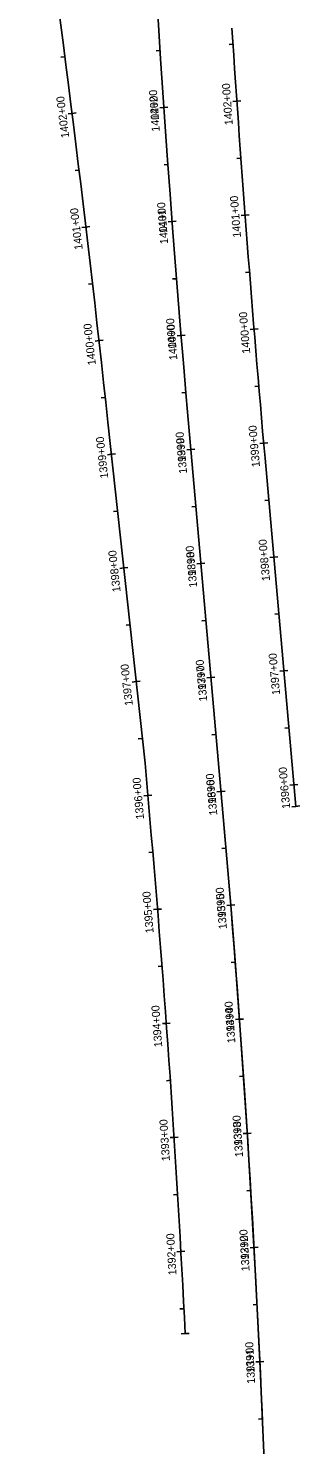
# Model space of a CAD drawing. Extents: x 596007 to 607538, y 326212 to 405053.
# Drawn here: x 602732 to 602976, y 363390 to 364628 of the extents above; entities that cross this region are included whole.
import ezdxf

# ---------------------------------------------------------------- set-up
doc = ezdxf.new("R2010")
doc.units = 0
doc.layers.add('P_ALI_200', color=7, linetype='Continuous')
doc.layers.add('P_ALI_200_Sta', color=7, linetype='Continuous')

msp = doc.modelspace()

# ---------------------------------------------------------------- linework, layer by layer
at = {"layer": 'P_ALI_200'}
for points in [[(602833.8, 363985.7), (602801.4, 364284)], [(602901.8, 363942.4), (602874.9, 364246.9)], [(602901.8, 363942.4), (602874.9, 364246.9)], [(602965.6, 363948), (602938.7, 364252.5)], [(602838.1, 363936.8), (602833.8, 363985.7)]]:
    msp.add_lwpolyline(points, dxfattribs=at)
for centre, radius, start, end in [((619326.8, 365700.7), 16516, 171.89148, 185.04999), ((619326.8, 365700.7), 16516, 171.89148, 185.04999), ((586893.5, 362570), 16000, 6.14964, 8.15156), ((619326.8, 365700.7), 16452, 183.73726, 185.04999), ((591430.5, 362928.7), 11452, 2.79426, 5.05), ((591430.5, 362928.7), 11516, 352.14213, 5.04999), ((591430.5, 362928.7), 11516, 2.35393, 5.04999)]:
    msp.add_arc(centre, radius, start, end, dxfattribs=at)
at = {"layer": 'P_ALI_200_Sta'}
for points in [[(602846.9, 364608.9), (602843.4, 364608.7)], [(602846.9, 364608.9), (602843.4, 364608.7)], [(602910.7, 364614.6), (602907.2, 364614.3)], [(602763.7, 364603.5), (602760.3, 364603.1)], [(602773.5, 364554.3), (602770, 364553.9)], [(602850.3, 364559), (602846.8, 364558.8)], [(602850.3, 364559), (602846.8, 364558.8)], [(602853.8, 364559.3), (602850.3, 364559)], [(602853.8, 364559.3), (602850.3, 364559)], [(602850.3, 364559), (602850.3, 364559)], [(602850.3, 364559), (602850.3, 364559)], [(602914.1, 364564.7), (602910.6, 364564.4)], [(602917.6, 364564.9), (602914.1, 364564.7)], [(602914.1, 364564.7), (602914.1, 364564.7)], [(602770, 364553.9), (602766.5, 364553.5)], [(602770, 364553.9), (602770, 364553.9)], [(602853.9, 364509.2), (602850.4, 364508.9)], [(602853.9, 364509.2), (602850.4, 364508.9)], [(602917.6, 364514.8), (602914.1, 364514.6)], [(602776.1, 364504.3), (602772.7, 364503.9)], [(602857.5, 364459.3), (602854, 364459)], [(602857.5, 364459.3), (602854, 364459)], [(602861, 364459.6), (602857.5, 364459.3)], [(602861, 364459.6), (602857.5, 364459.3)], [(602857.5, 364459.3), (602857.5, 364459.3)], [(602857.5, 364459.3), (602857.5, 364459.3)], [(602921.3, 364464.9), (602917.8, 364464.7)], [(602924.8, 364465.2), (602921.3, 364464.9)], [(602921.3, 364464.9), (602921.3, 364464.9)], [(602782.1, 364454.6), (602778.6, 364454.2)], [(602785.6, 364455.1), (602782.1, 364454.6)], [(602782.1, 364454.6), (602782.1, 364454.6)], [(602861.4, 364409.4), (602857.9, 364409.2)], [(602861.4, 364409.4), (602857.9, 364409.2)], [(602925.1, 364415.1), (602921.6, 364414.8)], [(602787.9, 364405), (602784.4, 364404.6)], [(602865.4, 364359.6), (602861.9, 364359.3)], [(602865.4, 364359.6), (602861.9, 364359.3)], [(602868.8, 364359.9), (602865.4, 364359.6)], [(602868.8, 364359.9), (602865.4, 364359.6)], [(602865.4, 364359.6), (602865.4, 364359.6)], [(602865.4, 364359.6), (602865.4, 364359.6)], [(602929.1, 364365.2), (602925.6, 364365)], [(602932.6, 364365.5), (602929.1, 364365.2)], [(602929.1, 364365.2), (602929.1, 364365.2)], [(602793.6, 364355.3), (602790.1, 364354.9)], [(602797.1, 364355.7), (602793.6, 364355.3)], [(602793.6, 364355.3), (602793.6, 364355.3)], [(602869.5, 364309.8), (602866, 364309.5)], [(602869.5, 364309.8), (602866, 364309.5)], [(602933.2, 364315.4), (602929.8, 364315.1)], [(602799.1, 364305.6), (602795.6, 364305.2)], [(602873.8, 364260), (602870.3, 364259.7)], [(602873.8, 364260), (602870.3, 364259.7)], [(602877.3, 364260.3), (602873.8, 364260)], [(602877.3, 364260.3), (602873.8, 364260)], [(602873.8, 364260), (602873.8, 364260)], [(602873.8, 364260), (602873.8, 364260)], [(602937.5, 364265.6), (602934, 364265.3)], [(602941, 364265.9), (602937.5, 364265.6)], [(602937.5, 364265.6), (602937.5, 364265.6)], [(602804.5, 364255.9), (602801, 364255.5)], [(602807.9, 364256.3), (602804.5, 364255.9)], [(602804.5, 364255.9), (602804.5, 364255.9)], [(602878.2, 364210.2), (602874.7, 364209.8)], [(602878.2, 364210.2), (602874.7, 364209.8)], [(602941.9, 364215.8), (602938.4, 364215.5)], [(602809.9, 364206.2), (602806.4, 364205.8)], [(602882.6, 364160.3), (602879.1, 364160)], [(602882.6, 364160.3), (602879.1, 364160)], [(602886.1, 364160.7), (602882.6, 364160.3)], [(602886.1, 364160.7), (602882.6, 364160.3)], [(602882.6, 364160.3), (602882.6, 364160.3)], [(602882.6, 364160.3), (602882.6, 364160.3)], [(602946.3, 364166), (602942.8, 364165.7)], [(602949.8, 364166.3), (602946.3, 364166)], [(602946.3, 364166), (602946.3, 364166)], [(602815.2, 364156.5), (602811.8, 364156.1)], [(602818.7, 364156.9), (602815.2, 364156.5)], [(602815.2, 364156.5), (602815.2, 364156.5)], [(602887, 364110.5), (602883.5, 364110.2)], [(602887, 364110.5), (602883.5, 364110.2)], [(602950.7, 364116.2), (602947.2, 364115.9)], [(602820.6, 364106.8), (602817.2, 364106.4)], [(602891.4, 364060.7), (602887.9, 364060.4)], [(602891.4, 364060.7), (602887.9, 364060.4)], [(602894.9, 364061), (602891.4, 364060.7)], [(602894.9, 364061), (602891.4, 364060.7)], [(602891.4, 364060.7), (602891.4, 364060.7)], [(602891.4, 364060.7), (602891.4, 364060.7)], [(602955.1, 364066.4), (602951.6, 364066.1)], [(602958.6, 364066.7), (602955.1, 364066.4)], [(602955.1, 364066.4), (602955.1, 364066.4)], [(602826, 364057.1), (602822.5, 364056.7)], [(602829.5, 364057.4), (602826, 364057.1)], [(602826, 364057.1), (602826, 364057.1)], [(602895.8, 364010.9), (602892.3, 364010.6)], [(602895.8, 364010.9), (602892.3, 364010.6)], [(602959.5, 364016.6), (602956, 364016.3)], [(602831.4, 364007.4), (602827.9, 364007)], [(602900.2, 363961.1), (602896.7, 363960.8)], [(602900.2, 363961.1), (602896.7, 363960.8)], [(602903.7, 363961.4), (602900.2, 363961.1)], [(602903.7, 363961.4), (602900.2, 363961.1)], [(602900.2, 363961.1), (602900.2, 363961.1)], [(602900.2, 363961.1), (602900.2, 363961.1)], [(602963.9, 363966.8), (602960.4, 363966.5)], [(602967.4, 363967.1), (602963.9, 363966.8)], [(602963.9, 363966.8), (602963.9, 363966.8)], [(602836.2, 363957.6), (602832.8, 363957.3)], [(602839.7, 363957.9), (602836.2, 363957.6)], [(602836.2, 363957.6), (602836.2, 363957.6)], [(602965.6, 363948), (602962.1, 363947.7)], [(602969.1, 363948.3), (602965.6, 363948)], [(602965.6, 363948), (602965.6, 363948)], [(602904.5, 363911.3), (602901, 363911)], [(602904.5, 363911.3), (602901, 363911)], [(602840.6, 363907.8), (602837.1, 363907.5)], [(602908.7, 363861.5), (602905.2, 363861.2)], [(602908.7, 363861.5), (602905.2, 363861.2)], [(602912.2, 363861.8), (602908.7, 363861.5)], [(602912.2, 363861.8), (602908.7, 363861.5)], [(602908.7, 363861.5), (602908.7, 363861.5)], [(602908.7, 363861.5), (602908.7, 363861.5)], [(602844.8, 363858), (602841.3, 363857.7)], [(602848.3, 363858.2), (602844.8, 363858)], [(602844.8, 363858), (602844.8, 363858)], [(602912.6, 363811.6), (602909.1, 363811.4)], [(602912.6, 363811.6), (602909.1, 363811.4)], [(602848.7, 363808.1), (602845.2, 363807.8)], [(602916.4, 363761.8), (602912.9, 363761.5)], [(602916.4, 363761.8), (602912.9, 363761.5)], [(602919.9, 363762), (602916.4, 363761.8)], [(602919.9, 363762), (602916.4, 363761.8)], [(602916.4, 363761.8), (602916.4, 363761.8)], [(602916.4, 363761.8), (602916.4, 363761.8)], [(602852.4, 363758.2), (602849, 363758)], [(602855.9, 363758.5), (602852.4, 363758.2)], [(602852.4, 363758.2), (602852.4, 363758.2)], [(602856, 363708.4), (602852.5, 363708.1)], [(602919.9, 363711.9), (602916.4, 363711.7)], [(602919.9, 363711.9), (602916.4, 363711.7)], [(602859.3, 363658.5), (602855.8, 363658.3)], [(602862.7, 363658.7), (602859.3, 363658.5)], [(602859.3, 363658.5), (602859.3, 363658.5)], [(602923.2, 363662), (602919.7, 363661.8)], [(602923.2, 363662), (602919.7, 363661.8)], [(602926.7, 363662.2), (602923.2, 363662)], [(602926.7, 363662.2), (602923.2, 363662)], [(602923.2, 363662), (602923.2, 363662)], [(602923.2, 363662), (602923.2, 363662)], [(602862.3, 363608.6), (602858.8, 363608.4)], [(602926.2, 363612.1), (602922.7, 363611.9)], [(602926.2, 363612.1), (602922.7, 363611.9)], [(602865.2, 363558.7), (602861.7, 363558.5)], [(602868.7, 363558.9), (602865.2, 363558.7)], [(602865.2, 363558.7), (602865.2, 363558.7)], [(602929.1, 363562.2), (602925.6, 363562)], [(602929.1, 363562.2), (602925.6, 363562)], [(602932.6, 363562.4), (602929.1, 363562.2)], [(602932.6, 363562.4), (602929.1, 363562.2)], [(602929.1, 363562.2), (602929.1, 363562.2)], [(602929.1, 363562.2), (602929.1, 363562.2)], [(602867.8, 363508.7), (602864.3, 363508.6)], [(602931.7, 363512.3), (602928.2, 363512.1)], [(602931.7, 363512.3), (602928.2, 363512.1)], [(602868.9, 363487), (602865.4, 363486.8)], [(602872.4, 363487.1), (602868.9, 363487)], [(602868.9, 363487), (602868.9, 363487)], [(602934.2, 363462.3), (602930.7, 363462.2)], [(602934.2, 363462.3), (602930.7, 363462.2)], [(602937.7, 363462.5), (602934.2, 363462.3)], [(602937.7, 363462.5), (602934.2, 363462.3)], [(602934.2, 363462.3), (602934.2, 363462.3)], [(602934.2, 363462.3), (602934.2, 363462.3)], [(602936.4, 363412.4), (602932.9, 363412.2)], [(602936.4, 363412.4), (602932.9, 363412.2)]]:
    msp.add_lwpolyline(points, dxfattribs=at)

# ---------------------------------------------------------------- texts
for s, height, rotation, p in [('1402+00', 7, 93.9595, (602910.5, 364543.9)), ('1402+00', 7, 97.1227, (602767.6, 364532.9)), ('1402+00', 7, 93.9637, (602846.7, 364538.2)), ('1402', 7, 93.9637, (602846, 364548.4)), ('1401+00', 7, 94.3077, (602917.7, 364445.6)), ('1401+00', 7, 96.7646, (602779.4, 364435.1)), ('1401+00', 7, 94.3106, (602854, 364439.9)), ('1401', 7, 94.3106, (602853.3, 364449.6)), ('1400+00', 7, 96.4065, (602790.9, 364334.1)), ('1400+00', 7, 94.6576, (602862.1, 364338.5)), ('1400', 7, 94.6576, (602861.2, 364348.7)), ('1400+00', 7, 94.656, (602925.8, 364344.1)), ('1399+00', 7, 96.1858, (602801.7, 364235.1)), ('1399+00', 7, 95.0045, (602870.6, 364239.2)), ('1399', 7, 95.0045, (602869.7, 364249.5)), ('1399+00', 7, 95.0043, (602934.3, 364244.9)), ('1398+00', 7, 96.1858, (602812.5, 364135.7)), ('1398+00', 7, 95.05, (602879.4, 364139.6)), ('1398+00', 7, 95.05, (602943.1, 364145.3)), ('1398', 7, 95.05, (602878.5, 364149.9)), ('1397+00', 7, 96.1858, (602823.2, 364036.3)), ('1397+00', 7, 95.05, (602888.2, 364040)), ('1397+00', 7, 95.05, (602951.9, 364045.7)), ('1397', 7, 95.05, (602887.3, 364050.3)), ('1396+00', 7, 95.05, (602833, 363936.9)), ('1396+00', 7, 95.05, (602897, 363940.4)), ('1396+00', 7, 95.05, (602960.7, 363946.1)), ('1396', 7, 95.05, (602896.1, 363950.6)), ('1395+81', 0.0000000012, 95.05, (602960.6, 363947.6)), ('1395+00', 7, 94.6543, (602841.4, 363837.3)), ('1395+00', 7, 94.646, (602905.4, 363840.8)), ('1395', 7, 94.646, (602904.5, 363851)), ('1394+00', 7, 94.1485, (602912.8, 363741.1)), ('1394+00', 7, 94.154, (602848.9, 363737.6)), ('1394', 7, 94.1485, (602912.1, 363751.4)), ('1393+00', 7, 93.6509, (602919.5, 363641.4)), ('1393+00', 7, 93.6537, (602855.6, 363637.9)), ('1393', 7, 93.6509, (602918.8, 363651.6)), ('1392+00', 7, 93.1534, (602925.2, 363541.6)), ('1392+00', 7, 93.1534, (602861.3, 363538.1)), ('1392', 7, 93.1534, (602924.7, 363551.9)), ('1391+28', 0.0000000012, 92.7943, (602863.9, 363486.7)), ('1391+00', 7, 92.6559, (602930, 363443.2)), ('1391', 7, 92.6559, (602929.6, 363452.9))]:
    msp.add_text(s, height=height, rotation=rotation, dxfattribs=at).set_placement(p)

doc.saveas('drawing.dxf')
